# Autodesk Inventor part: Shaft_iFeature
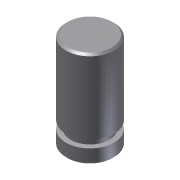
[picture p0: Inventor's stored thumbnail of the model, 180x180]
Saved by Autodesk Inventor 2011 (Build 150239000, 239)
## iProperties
Created: 2008-06
Part Number: Shaft_iFeature
Document SubType Name: Modeling
Designer: CADCIM
Density: 1 g/cm^3
Author: CADCIM
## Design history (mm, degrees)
sketch "Sketch1"
  geometry: C1 r 25 at (0, 0); 1 further point
  constraints: 1 centre point, 1 coincident, 1 other
  dimensions: "d0" = 50 diameter of C1
extrude "Extrusion1" new body sketch "Sketch1" distance "d1" = 100; taper "d2" = 0 deg
chamfer "Chamfer1" distance "d3" = 2; stored, may be unused: second distance "d4" = 2, angle "d5" = 45 deg
sketch "Sketch2"
  geometry: L1 (-25, 23)-(-20, 23); L2 (-20, 23)-(-20, 15); L3 (-20, 15)-(-25, 15); L4 (-25, 15)-(-25, 23); L5 (0, -1.4)-(0, 8.4) reference; 1 further point
  constraints: 8 end point, 2 parallel, 1 horizontal, 1 perpendicular, 1 point on line, 1 other
  dimensions: "d9" = 8 distance of L3.end L1.start; "d10" = 20 distance from line of point (0, 0) L2; "d11" = 15 distance from line of L3 point (0, 0); "d13" = 25 distance from line of point (0, 0) L4
revolve "Revolution1" sketch "Sketch2" stored, may be unused: angle "d12" = 90 deg
body "Solid1"
